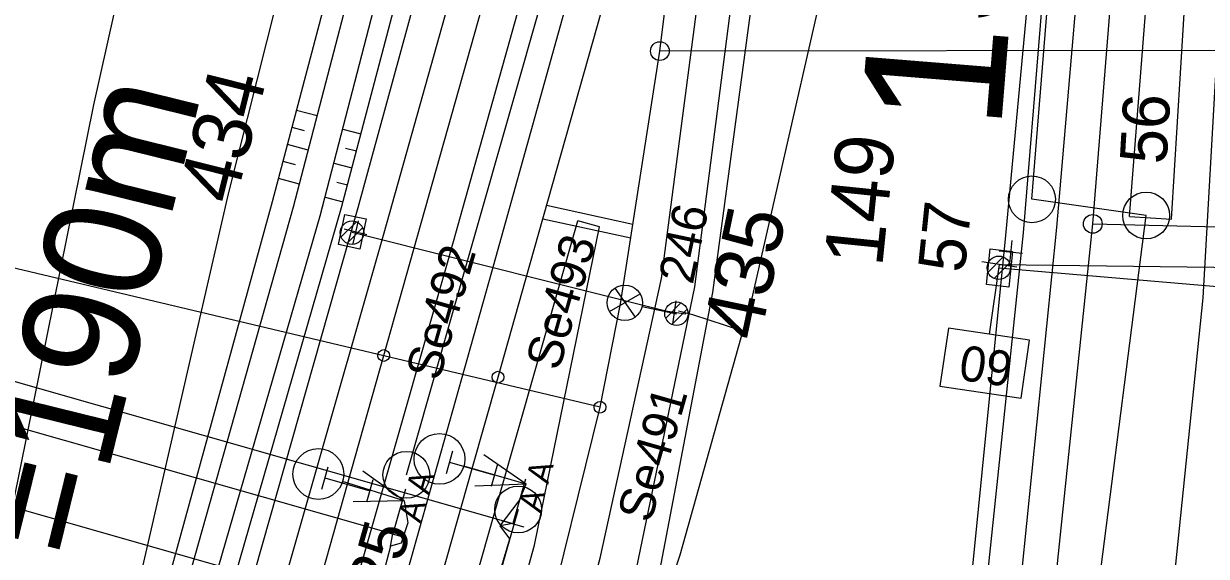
# Model space of a CAD drawing. Extents: x -598638 to -597933, y -1164002 to -1161904.
# Drawn here: x -598296.5 to -598246.1, y -1163336.1 to -1163313.4 of the extents above; entities that cross this region are included whole.
import ezdxf

# ---------------------------------------------------------------- set-up
doc = ezdxf.new("R2010")
doc.units = 0
for name, color, linetype in [('Vrstva 1', 7, 'Continuous'), ('Vrstva 11', 7, 'Continuous'), ('Vrstva 12', 7, 'Continuous'), ('Vrstva 25', 7, 'Continuous'), ('Vrstva 26', 7, 'Continuous'), ('Vrstva 28', 7, 'Continuous'), ('Vrstva 3', 7, 'Continuous'), ('Vrstva 4', 7, 'Continuous'), ('Vrstva 43', 7, 'Continuous'), ('Vrstva 44', 7, 'Continuous'), ('Vrstva 48', 7, 'Continuous'), ('Vrstva 49', 7, 'Continuous'), ('Vrstva 5', 7, 'Continuous'), ('Vrstva 51', 7, 'Continuous'), ('Vrstva 6', 7, 'Continuous'), ('Vrstva 7', 7, 'Continuous')]:
    doc.layers.add(name, color=color, linetype=linetype)

msp = doc.modelspace()

# ---------------------------------------------------------------- linework, layer by layer
at = {"layer": 'Vrstva 1'}
for p, q in [((-598271.932, -1163329.761), (-598436.447, -1163290.693)), ((-598172.852, -1163314.447), (-598269.379, -1163314.559)), ((-598250.9, -1163321.936), (-598177.525, -1163323.686))]:
    msp.add_line(p, q, dxfattribs=at)
for points in [[(-598250.9, -1163321.936), (-598249.53, -1163304.978), (-598248.914, -1163297.297), (-598247.877, -1163284.361), (-598246.649, -1163269.02)], [(-598290.948, -1163362.176), (-598285.982, -1163344.65), (-598282.717, -1163333.052), (-598281.168, -1163327.552), (-598279.885, -1163323.01), (-598271.302, -1163292.589), (-598266.808, -1163276.648)], [(-598259.161, -1163402.069), (-598257.506, -1163395.492), (-598254.014, -1163379.874), (-598251.435, -1163366.348), (-598248.154, -1163344.226), (-598246.19, -1163325.096), (-598245.046, -1163305.011), (-598244.933, -1163298.014), (-598244.77, -1163287.888)], [(-598286.211, -1163363.553), (-598281.229, -1163345.959), (-598277.392, -1163332.383), (-598276.288, -1163328.478), (-598275.12, -1163324.336), (-598270.9, -1163309.421)], [(-598269.379, -1163314.559), (-598268.795, -1163309.856)], [(-598275.08, -1163342.522), (-598274.389, -1163339.723), (-598271.932, -1163329.761), (-598271.055, -1163325.346), (-598269.379, -1163314.559)], [(-598264.28, -1163400.716), (-598262.877, -1163395.251), (-598259.069, -1163378.617), (-598256.287, -1163364.167), (-598253.132, -1163343.401), (-598250.9, -1163321.936)]]:
    msp.add_lwpolyline(points, dxfattribs=at)
for centre, radius in [((-598269.379, -1163314.559), 0.4), ((-598250.9, -1163321.936), 0.4), ((-598281.168, -1163327.553), 0.25), ((-598276.288, -1163328.479), 0.25), ((-598271.932, -1163329.762), 0.25)]:
    msp.add_circle(centre, radius, dxfattribs=at)
at = {"layer": 'Vrstva 11'}
for p, q in [((-598282.981, -1163322.494), (-598282.335, -1163321.848)), ((-598282.721, -1163322.764), (-598282.066, -1163322.109)), ((-598255.371, -1163323.994), (-598254.725, -1163323.348)), ((-598255.111, -1163324.264), (-598254.456, -1163323.609)), ((-598269.131, -1163325.954), (-598268.485, -1163325.308)), ((-598268.871, -1163326.224), (-598268.216, -1163325.569))]:
    msp.add_line(p, q, dxfattribs=at)
for points in [[(-598268.67, -1163325.77), (-598282.52, -1163322.31)], [(-598254.91, -1163323.81), (-598237.59, -1163325.29)]]:
    msp.add_lwpolyline(points, dxfattribs=at)
for centre in [(-598282.52, -1163322.31), (-598254.91, -1163323.81), (-598268.67, -1163325.77)]:
    msp.add_circle(centre, 0.5, dxfattribs=at)
at = {"layer": 'Vrstva 12'}
for points in [[(-598281.91, -1163321.72), (-598282.18, -1163323.01), (-598283.1, -1163322.82), (-598282.83, -1163321.54), (-598281.91, -1163321.72)], [(-598254.32, -1163323.12), (-598254.48, -1163324.64), (-598255.44, -1163324.52), (-598255.28, -1163323), (-598254.32, -1163323.12)]]:
    msp.add_lwpolyline(points, dxfattribs=at)
at = {"layer": 'Vrstva 25'}
for p, q in [((-598271.306, -1163324.684), (-598270.433, -1163325.913)), ((-598271.531, -1163325.673), (-598270.222, -1163324.925)), ((-598270.138, -1163325.46), (-598268.67, -1163325.77))]:
    msp.add_line(p, q, dxfattribs=at)
msp.add_circle((-598270.875, -1163325.302), 0.754, dxfattribs=at)
at = {"layer": 'Vrstva 26'}
for points in [[(-598273.816, -1163355.578), (-598271.677, -1163346.374), (-598270.289, -1163341.485), (-598268.518, -1163336.06), (-598265.457, -1163325.157), (-598262.629, -1163312.811), (-598258.667, -1163293.697), (-598257.35, -1163282.225), (-598255.678, -1163268.505), (-598254.603, -1163254.848), (-598253.891, -1163243.597), (-598253.428, -1163235.813)], [(-598265.886, -1163326.504), (-598267.977, -1163325.82), (-598268.588, -1163325.667)]]:
    msp.add_lwpolyline(points, dxfattribs=at)
at = {"layer": 'Vrstva 28'}
for points in [[(-598274.1, -1163355.29), (-598280.63, -1163353.04), (-598280.01, -1163350.81), (-598276.94, -1163339.27), (-598275.78, -1163335.38), (-598276.19, -1163334.83), (-598275.38, -1163333.76), (-598275.09, -1163333.04)], [(-598280.29, -1163333.76), (-598280.13, -1163334.7), (-598280.42, -1163335.56), (-598280.87, -1163335.69), (-598280.78, -1163335.17)], [(-598275.66, -1163334.73), (-598276.19, -1163334.83)], [(-598280.87, -1163335.69), (-598282.75, -1163342.88), (-598282.94, -1163344.95), (-598283.45, -1163346.41), (-598287.18, -1163358.85), (-598290.82, -1163371.16), (-598291.38, -1163373.96), (-598293.38, -1163378.64), (-598298.74, -1163391.6), (-598301.27, -1163396.71), (-598302.38, -1163400.04), (-598304.98, -1163404.12), (-598309.67, -1163412.34), (-598310, -1163412.93)]]:
    msp.add_lwpolyline(points, dxfattribs=at)
at = {"layer": 'Vrstva 3'}
for p, q in [((-598278.49, -1163332.592), (-598278.218, -1163331.63)), ((-598275.09, -1163333.04), (-598276.886, -1163331.8)), ((-598283.815, -1163333.262), (-598283.544, -1163332.3)), ((-598278.354, -1163332.111), (-598276.43, -1163332.655)), ((-598275.09, -1163333.04), (-598277.741, -1163332.271)), ((-598276.566, -1163333.136), (-598276.294, -1163332.174)), ((-598283.679, -1163332.78), (-598281.755, -1163333.324)), ((-598280.29, -1163333.76), (-598282.061, -1163332.485)), ((-598280.29, -1163333.76), (-598282.925, -1163332.938)), ((-598281.89, -1163333.804), (-598281.619, -1163332.842)), ((-598275.09, -1163333.04), (-598277.27, -1163333.126)), ((-598280.29, -1163333.76), (-598282.472, -1163333.803))]:
    msp.add_line(p, q, dxfattribs=at)
for centre in [(-598278.785, -1163331.969), (-598283.957, -1163332.613)]:
    msp.add_circle(centre, 1.084, dxfattribs=at)
at = {"layer": 'Vrstva 4'}
for points in [[(-598398.167, -1163553.239), (-598376.487, -1163515.918), (-598348.795, -1163467.979), (-598339.716, -1163452.202), (-598323.266, -1163423.236), (-598308.372, -1163396.471), (-598302.715, -1163384.123), (-598298.324, -1163372.137), (-598289.593, -1163344.221), (-598282.967, -1163321.229), (-598274.797, -1163290.285), (-598269.404, -1163272.781), (-598266.519, -1163258.633), (-598263.896, -1163241.651), (-598261.185, -1163218.05), (-598260.503, -1163217.001), (-598259.092, -1163201.513), (-598258.163, -1163186.176), (-598256.557, -1163141.317), (-598256.485, -1163129.008), (-598255.651, -1163108.451), (-598254.34, -1163087.718), (-598253.319, -1163075.132)], [(-598307.376, -1163503.64), (-598306.256, -1163500.72), (-598304.527, -1163496.743), (-598299.478, -1163486.144), (-598290.117, -1163465.204), (-598280.795, -1163442.724), (-598274.814, -1163425.66), (-598269.09, -1163405.616), (-598262.907, -1163380.487), (-598260.225, -1163366.071), (-598256.638, -1163342.661), (-598254.612, -1163322.432), (-598252.977, -1163304.928), (-598251.437, -1163287.268), (-598250.068, -1163266.224), (-598248.818, -1163245.446), (-598248.467, -1163214.545), (-598248.623, -1163173.63), (-598248.072, -1163131.254), (-598247.596, -1163128.349)], [(-598388.69, -1163572.819), (-598382.701, -1163561.089), (-598361.383, -1163524.292), (-598334.6, -1163477.579), (-598308.353, -1163432.12), (-598292.471, -1163404.257), (-598285.937, -1163390.16), (-598281.631, -1163378.652), (-598277.216, -1163365.008), (-598272.579, -1163348.284), (-598269.387, -1163336.75), (-598267.113, -1163324.869), (-598262.674, -1163291.919), (-598258.642, -1163259.137), (-598254.182, -1163220.99), (-598251.647, -1163201.068), (-598250.766, -1163187.503), (-598249.671, -1163144.519), (-598248.922, -1163130.776), (-598248.69, -1163130.313)]]:
    msp.add_lwpolyline(points, dxfattribs=at)
at = {"layer": 'Vrstva 43'}
for centre in [(-598253.497, -1163320.887), (-598248.62, -1163321.577), (-598280.199, -1163332.648), (-598275.426, -1163334.13)]:
    msp.add_circle(centre, 1, dxfattribs=at)
at = {"layer": 'Vrstva 44'}
for points in [[(-598295.758, -1163493.483), (-598278.118, -1163452.874), (-598264.209, -1163410.565), (-598254.468, -1163367.19), (-598248.62, -1163321.577), (-598253.497, -1163320.887), (-598249.615, -1163272.581), (-598247.635, -1163222.481), (-598247.486, -1163176.779), (-598247.442, -1163130.148), (-598244.014, -1163084.171), (-598235.33, -1163037.762), (-598224.817, -1163002.559), (-598219.379, -1163002.169), (-598206.652, -1162968.487), (-598191.401, -1162936.053), (-598173.754, -1162904.506), (-598155.689, -1162873.083), (-598136.14, -1162838.446), (-598116.776, -1162804.197)], [(-598280.199, -1163332.648), (-598271.397, -1163301.809), (-598265.446, -1163302.712), (-598259.208, -1163252.741), (-598251.788, -1163176.385), (-598250.383, -1163130.296), (-598247.948, -1163083.491), (-598241.007, -1163044.927)], [(-598275.426, -1163334.13), (-598284.517, -1163365.994), (-598293.775, -1163392.227), (-598310.061, -1163422.881)]]:
    msp.add_lwpolyline(points, dxfattribs=at)
at = {"layer": 'Vrstva 48'}
for p, q in [((-598284.009, -1163317.33), (-598284.889, -1163317.097)), ((-598284.551, -1163317.963), (-598285.081, -1163317.822)), ((-598282.913, -1163317.889), (-598282.139, -1163318.094)), ((-598284.387, -1163318.782), (-598285.273, -1163318.547)), ((-598282.793, -1163318.697), (-598282.331, -1163318.819)), ((-598284.932, -1163319.413), (-598285.464, -1163319.272)), ((-598283.29, -1163319.341), (-598282.522, -1163319.544)), ((-598284.766, -1163320.233), (-598285.656, -1163319.997)), ((-598283.172, -1163320.148), (-598282.713, -1163320.269)), ((-598283.666, -1163320.793), (-598282.905, -1163320.994))]:
    msp.add_line(p, q, dxfattribs=at)
at = {"layer": 'Vrstva 49'}
for points in [[(-598299.445, -1163361.058), (-598297.068, -1163359.059), (-598293.068, -1163343.621), (-598287.79, -1163320.649), (-598279.637, -1163288.312), (-598274.636, -1163271.434), (-598271.523, -1163257.595), (-598269.283, -1163241.904), (-598267.104, -1163218.072), (-598264.127, -1163206.783), (-598263.144, -1163204.971), (-598260.62, -1163202.843), (-598259.578, -1163186.018), (-598258.253, -1163141.176), (-598259.192, -1163127.718), (-598260.075, -1163119.279), (-598261.182, -1163115.692), (-598261.349, -1163113.122), (-598258.894, -1163101.538), (-598255.65, -1163087.809), (-598254.518, -1163075.132), (-598252.098, -1163061.479), (-598247.841, -1163044.835)], [(-598309.446, -1163203.262), (-598316.229, -1163215.539), (-598313.873, -1163217.741), (-598321.933, -1163233.799), (-598326.308, -1163254.29), (-598324.871, -1163281.374), (-598324.668, -1163290.005), (-598320.258, -1163307.426), (-598325.507, -1163312.636), (-598323.584, -1163327.934), (-598325.353, -1163339.082), (-598298.967, -1163343.623), (-598293.544, -1163316.86), (-598287.625, -1163290.34), (-598280.443, -1163265.616), (-598276.989, -1163242.095), (-598274.987, -1163221.639), (-598274.592, -1163211.298), (-598290.163, -1163206.434), (-598302.523, -1163205.338), (-598306.323, -1163207.572)], [(-598350.075, -1163469.161), (-598350.962, -1163468.642), (-598341.128, -1163451.449), (-598324.91, -1163422.41), (-598309.936, -1163395.461), (-598304.358, -1163383.215), (-598300.139, -1163371.399), (-598292.224, -1163343.911), (-598285.916, -1163320.98), (-598277.492, -1163289.124), (-598272.642, -1163272.084), (-598269.771, -1163257.778), (-598267.544, -1163241.285), (-598265.728, -1163218.657), (-598264.511, -1163217.412), (-598261.185, -1163218.05)], [(-598350.962, -1163468.642), (-598340.803, -1163451.583), (-598324.406, -1163422.648), (-598309.58, -1163395.796), (-598303.887, -1163383.446), (-598299.666, -1163371.582), (-598291.401, -1163343.859), (-598285.02, -1163321.209), (-598276.751, -1163289.495), (-598271.739, -1163271.843), (-598268.729, -1163258.218), (-598266.553, -1163241.22), (-598264.463, -1163218.64)], [(-598350.075, -1163469.161), (-598340.252, -1163451.87), (-598323.84, -1163422.849), (-598308.915, -1163396.15), (-598303.181, -1163383.749), (-598299.003, -1163371.924), (-598290.374, -1163343.997), (-598283.872, -1163321.586), (-598275.648, -1163289.867), (-598270.185, -1163272.379), (-598267.391, -1163258.396), (-598265.172, -1163241.341), (-598262.635, -1163218.663), (-598264.463, -1163218.64)]]:
    msp.add_lwpolyline(points, dxfattribs=at)
at = {"layer": 'Vrstva 5'}
msp.add_line((-598254.147, -1163323.78), (-598255.632, -1163323.562), dxfattribs=at)
for points in [[(-598254.89, -1163323.671), (-598255.329, -1163326.639), (-598257.059, -1163326.383), (-598257.425, -1163328.856), (-598253.962, -1163329.368), (-598253.597, -1163326.894), (-598255.329, -1163326.639)], [(-598254.89, -1163323.671), (-598190.734, -1163324.471)]]:
    msp.add_lwpolyline(points, dxfattribs=at)
at = {"layer": 'Vrstva 51'}
for points in [[(-598397.431, -1163553.318), (-598375.745, -1163515.943), (-598348.098, -1163468.333), (-598322.38, -1163423.533), (-598307.542, -1163396.818), (-598301.86, -1163384.541), (-598297.285, -1163372.341), (-598293.283, -1163359.379), (-598288.845, -1163344.448), (-598282.25, -1163321.235), (-598273.825, -1163290.423), (-598265.756, -1163258.778), (-598260.545, -1163219.203), (-598259.744, -1163217.171), (-598258.57, -1163201.891), (-598257.659, -1163186.255), (-598256.038, -1163142.193), (-598255.793, -1163128.623), (-598255.065, -1163108.27), (-598253.781, -1163088.998), (-598252.62, -1163075.466)], [(-598396.078, -1163554.151), (-598374.443, -1163516.599), (-598347.031, -1163469.014), (-598321.218, -1163424.261), (-598306.253, -1163397.723), (-598300.608, -1163385.153), (-598295.814, -1163372.93), (-598291.849, -1163359.988), (-598287.46, -1163344.41), (-598281.154, -1163322.32), (-598272.412, -1163291.197), (-598264.229, -1163259.135), (-598258.972, -1163219.27), (-598257.327, -1163201.644), (-598256.369, -1163186.491), (-598254.79, -1163142.649), (-598254.397, -1163128.629), (-598253.571, -1163108.317), (-598252.585, -1163090.153), (-598250.983, -1163076.012)], [(-598384.985, -1163560.822), (-598363.176, -1163523.063), (-598335.955, -1163475.581), (-598310.179, -1163431.066), (-598295.149, -1163404.135), (-598288.465, -1163389.583), (-598283.96, -1163377.815), (-598279.772, -1163364.473), (-598275.196, -1163348.33), (-598271.933, -1163336.198), (-598269.31, -1163324.265), (-598265.084, -1163292.029), (-598261.053, -1163259.678), (-598256.104, -1163220.296), (-598254.426, -1163201.671), (-598253.667, -1163187.936), (-598252.018, -1163143.494), (-598251.534, -1163128.863), (-598250.791, -1163108.998), (-598250.069, -1163094.383), (-598248.218, -1163076.729)], [(-598305.922, -1163504.285), (-598297.335, -1163487.137), (-598287.92, -1163465.981), (-598279.035, -1163443.103), (-598273.208, -1163425.978), (-598267.2, -1163406.108), (-598261.011, -1163380.887), (-598258.166, -1163366.304), (-598254.569, -1163343.143), (-598252.435, -1163322.084), (-598250.965, -1163305.051), (-598249.488, -1163286.133), (-598247.962, -1163266.793), (-598246.718, -1163245.404), (-598246.637, -1163214.417), (-598246.633, -1163173.748), (-598246.347, -1163129.422), (-598245.484, -1163112.939), (-598244.076, -1163096.672), (-598241.475, -1163076.865)], [(-598298.888, -1163486.593), (-598289.113, -1163465.583), (-598279.905, -1163442.964), (-598274.107, -1163425.699), (-598268.268, -1163405.757), (-598262.238, -1163380.596), (-598259.701, -1163366.461), (-598255.999, -1163342.847), (-598253.859, -1163322.319), (-598252.407, -1163304.609), (-598250.982, -1163286.31), (-598249.458, -1163266.6), (-598248.128, -1163245.447), (-598247.963, -1163214.31), (-598248.01, -1163173.778), (-598247.475, -1163130.652), (-598247.596, -1163128.349), (-598246.685, -1163112.866), (-598245.177, -1163096.514), (-598242.921, -1163076.624)], [(-598389.422, -1163572.47), (-598383.242, -1163561.018), (-598361.933, -1163523.985), (-598335.337, -1163477.363), (-598309.065, -1163431.797), (-598293.626, -1163404.644), (-598286.924, -1163390.082), (-598282.523, -1163378.361), (-598278.252, -1163364.663), (-598273.758, -1163348.557), (-598270.372, -1163336.656), (-598267.892, -1163324.623), (-598263.657, -1163291.858), (-598259.724, -1163259.57), (-598255.007, -1163220.516), (-598252.865, -1163201.196), (-598252.034, -1163187.935), (-598250.643, -1163143.798), (-598250.023, -1163129.244), (-598249.184, -1163109.078), (-598248.423, -1163094.475), (-598246.693, -1163077.089)], [(-598405.752, -1163584.856), (-598406.565, -1163584.53), (-598399.621, -1163567.58), (-598392.991, -1163554.623), (-598370.643, -1163515.908), (-598344.594, -1163470.689), (-598318.975, -1163426.348), (-598303.98, -1163399.626), (-598297.883, -1163386.424), (-598293.238, -1163374.41), (-598289.078, -1163361.082), (-598284.443, -1163344.622), (-598278.418, -1163323.499), (-598273.781, -1163306.93), (-598268.859, -1163289.076)], [(-598405.752, -1163584.856), (-598398.056, -1163568.29), (-598390.909, -1163555.148), (-598369.148, -1163517.525), (-598342.954, -1163471.89), (-598317.093, -1163427.101), (-598302.088, -1163400.435), (-598295.928, -1163387.037), (-598291.26, -1163374.845), (-598287.219, -1163361.857), (-598282.441, -1163344.932), (-598276.551, -1163323.978), (-598272.024, -1163307.744), (-598269.633, -1163298.161), (-598267.957, -1163289.279), (-598268.859, -1163289.076)], [(-598249.328, -1163321.623), (-598248.023, -1163304.979), (-598247.126, -1163293.411), (-598246.23, -1163293.485)], [(-598249.328, -1163321.623), (-598247.542, -1163321.734), (-598246.515, -1163305.107), (-598246.23, -1163293.485)], [(-598427.315, -1163664.7), (-598428.18, -1163664.394), (-598425.636, -1163654.614), (-598418.444, -1163627.396), (-598410.117, -1163604.122), (-598400.961, -1163581.084), (-598395.464, -1163569.593), (-598389.92, -1163559.339), (-598367.418, -1163520.243), (-598340.118, -1163472.9), (-598314.456, -1163428.342), (-598299.482, -1163401.608), (-598293.182, -1163387.859), (-598288.581, -1163375.919), (-598284.449, -1163362.711), (-598279.879, -1163346.369), (-598272.886, -1163321.804)], [(-598427.315, -1163664.7), (-598423.952, -1163654.666), (-598416.386, -1163628.209), (-598407.715, -1163605.193), (-598398.502, -1163582.119), (-598393.545, -1163570.609), (-598388.107, -1163560.38), (-598365.543, -1163521.215), (-598338.352, -1163474.013), (-598312.732, -1163429.553), (-598297.643, -1163402.904), (-598291.214, -1163388.734), (-598286.704, -1163376.829), (-598282.472, -1163363.328), (-598277.874, -1163346.939), (-598274.73, -1163335.645), (-598271.957, -1163322.057), (-598272.886, -1163321.804)]]:
    msp.add_lwpolyline(points, dxfattribs=at)
at = {"layer": 'Vrstva 6'}
for p, q in [((-598314.124, -1163323.749), (-598275.66, -1163334.73)), ((-598319.244, -1163324.189), (-598280.78, -1163335.17)), ((-598310.214, -1163330.239), (-598271.75, -1163341.22)), ((-598275.116, -1163332.826), (-598275.66, -1163334.73)), ((-598280.236, -1163333.266), (-598280.78, -1163335.17)), ((-598276.14, -1163334.593), (-598275.179, -1163334.867)), ((-598281.26, -1163335.033), (-598280.299, -1163335.307))]:
    msp.add_line(p, q, dxfattribs=at)
at = {"layer": 'Vrstva 7'}
for p, q in [((-598274.215, -1163321.138), (-598270.526, -1163321.943)), ((-598274.379, -1163321.717), (-598270.619, -1163322.537)), ((-598281.883, -1163322.403), (-598282.855, -1163322.167)), ((-598282.251, -1163321.799), (-598282.487, -1163322.771)), ((-598254.353, -1163322.638), (-598254.451, -1163323.634)), ((-598254.9, -1163323.087), (-598253.904, -1163323.185)), ((-598268.692, -1163325.221), (-598268.834, -1163326.211)), ((-598268.268, -1163325.787), (-598269.258, -1163325.645))]:
    msp.add_line(p, q, dxfattribs=at)

# ---------------------------------------------------------------- texts
at = {"layer": 'Vrstva 1'}
msp.add_text('r=190m', height=5, rotation=76.1424, dxfattribs=at).set_placement((-598294.428, -1163338.601))
at = {"layer": 'Vrstva 11'}
for s, rotation, p in [('434', 75.8609, (-598287.524, -1163321.164)), ('149', 84.144, (-598259.89, -1163323.81)), ('435', 78.1517, (-598265.117, -1163326.989))]:
    msp.add_text(s, height=2.5, rotation=rotation, dxfattribs=at).set_placement(p)
at = {"layer": 'Vrstva 25'}
msp.add_text('246', height=1.5, rotation=78.0888, dxfattribs=at).set_placement((-598267.98, -1163324.561))
at = {"layer": 'Vrstva 43'}
for s, rotation, p in [('56', 86.7401, (-598247.756, -1163319.415)), ('57', 84.0635, (-598256.378, -1163324.058)), ('425', 74.2171, (-598281.208, -1163339.279))]:
    msp.add_text(s, height=2, rotation=rotation, dxfattribs=at).set_placement(p)
at = {"layer": 'Vrstva 5'}
msp.add_text('60', height=1.5, rotation=171.5879, dxfattribs=at).set_placement((-598254.241, -1163327.421))
at = {"layer": 'Vrstva 6'}
for s, height, p in [('Se493', 1.5, (-598273.685, -1163328.253)), ('Se492', 1.5, (-598278.805, -1163328.693)), ('Se491', 1.5, (-598269.775, -1163334.743)), ('  A A', 1, (-598274.698, -1163335.005)), ('  A A', 1, (-598279.818, -1163335.445))]:
    msp.add_text(s, height=height, rotation=74.0672, dxfattribs=at).set_placement(p)
at = {"layer": 'Vrstva 7'}
msp.add_text('153,5', height=6, rotation=85.3812, dxfattribs=at).set_placement((-598254.828, -1163318.007))

doc.saveas('drawing.dxf')
